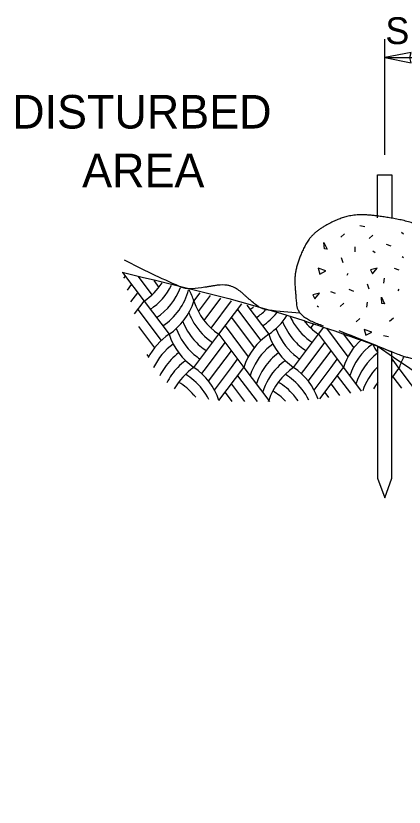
# Model space of a CAD drawing. Extents: x 99862 to 103680, y 99470 to 102076.
# Drawn here: x 101486.6 to 101717.9, y 100885.4 to 101357.1 of the extents above; entities that cross this region are included whole.
import ezdxf

# ---------------------------------------------------------------- set-up
doc = ezdxf.new("R2010")
doc.units = 0
for name, color, linetype in [('Level 1', 7, 'Continuous'), ('Level 15', 7, 'Continuous'), ('Level 2', 7, 'Continuous'), ('Level 20', 7, 'Continuous'), ('Level 5', 7, 'Continuous'), ('Level 8', 7, 'Continuous')]:
    doc.layers.add(name, color=color, linetype=linetype)

msp = doc.modelspace()

# ---------------------------------------------------------------- linework, layer by layer
at = {"layer": 'Level 1'}
msp.add_line((101701.88, 101160.32), (101681.85, 101168.11), dxfattribs=at)
msp.add_open_spline([(101679, 101169.6), (101713.94, 101155.29), (101722.33, 101152.8), (101733.67, 101150.75), (101742.6, 101156.76), (101752.6, 101167.59), (101757.92, 101185.54), (101757.37, 101195.19), (101755.63, 101199.86), (101754.11, 101209.17), (101741.6, 101223.5), (101725.73, 101233.48), (101704.82, 101237.69), (101688.7, 101238.98), (101676.01, 101235.17), (101662.34, 101226.63), (101656.02, 101214.64), (101652.47, 101202.67), (101653.18, 101191.71), (101654.52, 101177.27), (101669.65, 101172.39)], degree=2, dxfattribs=at)
at = {"layer": 'Level 15'}
for p, q in [((101706.31, 101274.26), (101706.31, 101343.26)), ((101706.31, 101332.26), (101960.08, 101332.26))]:
    msp.add_line(p, q, dxfattribs=at)
msp.add_lwpolyline([(101706.31, 101332.26), (101722.04, 101329.18), (101721.31, 101332.26), (101722.04, 101335.35)], close=True, dxfattribs=at)
at = {"layer": 'Level 2'}
for p, q in [((101691.48, 101232.14), (101694.43, 101231.6)), ((101680.12, 101225.26), (101682.39, 101227.21)), ((101716.35, 101228.18), (101717.6, 101227.24)), ((101697, 101224.35), (101699.28, 101226.31)), ((101688.6, 101219.45), (101688.6, 101216.45)), ((101707.16, 101221.04), (101709.95, 101219.92)), ((101681.66, 101209.93), (101680.65, 101212.76)), ((101699.32, 101216.92), (101700.57, 101215.98)), ((101716.67, 101213.64), (101717.45, 101213.01)), ((101684.39, 101203.47), (101683.77, 101202.37)), ((101711.99, 101206.71), (101714.77, 101205.59)), ((101705.95, 101200.65), (101705.65, 101197.67)), ((101684.89, 101194.07), (101687.72, 101193.06)), ((101697.09, 101194.23), (101696.08, 101197.06)), ((101714.79, 101194.24), (101714.16, 101193.14)), ((101674, 101192.83), (101676.78, 101191.71)), ((101679.69, 101183.86), (101681.89, 101185.9)), ((101695.84, 101186.32), (101695.55, 101183.34)), ((101666.18, 101184.23), (101666.96, 101183.6)), ((101689.31, 101174.72), (101691.59, 101176.67)), ((101709.21, 101175.02), (101711.49, 101176.98)), ((101705.65, 101166.51), (101708.61, 101165.98)), ((101702.13, 101160.21), (101702.13, 101081.58)), ((101710.49, 101156.68), (101702.13, 101160.21)), ((101710.49, 101081.58), (101710.49, 101156.68)), ((101702.13, 101081.58), (101706.31, 101069.69)), ((101706.31, 101069.69), (101710.49, 101081.58))]:
    msp.add_line(p, q, dxfattribs=at)
msp.add_lwpolyline([(101702.13, 101236.77), (101702.13, 101262.26), (101710.49, 101262.26), (101710.49, 101236.54)], dxfattribs=at)
for points in [[(101670.09, 101221.93), (101671.96, 101218.02), (101670.4, 101218.17)], [(101666.65, 101206.6), (101667.74, 101203.16), (101671.34, 101205.03)], [(101697.91, 101205.71), (101699, 101203.37), (101701.82, 101206.65)], [(101663.52, 101190.79), (101664.62, 101188.45), (101667.43, 101191.73)], [(101704.34, 101189.31), (101706.22, 101185.4), (101704.65, 101185.55)], [(101694, 101170.15), (101695.1, 101166.71), (101698.69, 101168.58)]]:
    msp.add_lwpolyline(points, close=True, dxfattribs=at)
at = {"layer": 'Level 5'}
for p, q in [((101550.2, 101204.14), (101562.99, 101187.09)), ((101550.9, 101200.67), (101551.85, 101201.94)), ((101559.45, 101201.71), (101567.64, 101190.79)), ((101568.69, 101199.29), (101571.72, 101195.25)), ((101553.02, 101193.61), (101555.56, 101196.99)), ((101555.15, 101186.55), (101559.28, 101192.04)), ((101592.69, 101187.09), (101596.38, 101192.02)), ((101595.36, 101180.76), (101602.58, 101190.39)), ((101557.28, 101179.48), (101562.99, 101187.09)), ((101562.99, 101187.09), (101577.84, 101167.29)), ((101598.8, 101175.45), (101608.78, 101188.76)), ((101602.88, 101170.99), (101614.99, 101187.13)), ((101607.54, 101167.29), (101621.19, 101185.5)), ((101624.16, 101184.72), (101637.23, 101167.29)), ((101559.28, 101182.14), (101573.18, 101163.6)), ((101618.67, 101182.14), (101632.58, 101163.6)), ((101614.96, 101177.19), (101628.5, 101159.14)), ((101559.58, 101171.83), (101569.11, 101159.14)), ((101611.25, 101172.24), (101625.06, 101153.83)), ((101662.28, 101170.99), (101664.16, 101173.49)), ((101666.93, 101167.29), (101670.08, 101171.49)), ((101671.6, 101170.97), (101684.45, 101153.83)), ((101592.69, 101147.5), (101607.54, 101167.29)), ((101607.54, 101167.29), (101622.38, 101147.5)), ((101652.08, 101147.5), (101666.93, 101167.29)), ((101666.93, 101167.29), (101681.78, 101147.5)), ((101681.67, 101167.44), (101687.9, 101159.14)), ((101600.11, 101147.5), (101611.25, 101162.34)), ((101659.51, 101147.5), (101670.64, 101162.34)), ((101691.37, 101164.4), (101691.98, 101163.6)), ((101607.54, 101147.5), (101614.96, 101157.4)), ((101666.93, 101147.5), (101674.36, 101157.4)), ((101564.57, 101155.29), (101565.66, 101153.83)), ((101614.96, 101147.5), (101618.67, 101152.45)), ((101674.36, 101147.5), (101678.07, 101152.45)), ((101710.49, 101152.62), (101714.79, 101146.88)), ((101710.49, 101151.04), (101711.08, 101151.83)), ((101717.16, 101153.63), (101717.47, 101153.22)), ((101597.34, 101143.8), (101600.11, 101147.5)), ((101601.42, 101139.34), (101607.54, 101147.5)), ((101604.86, 101134.03), (101614.96, 101147.5)), ((101607.56, 101127.73), (101622.38, 101147.5)), ((101622.38, 101147.5), (101637.23, 101127.7)), ((101656.74, 101143.8), (101659.51, 101147.5)), ((101660.81, 101139.34), (101666.93, 101147.5)), ((101664.26, 101134.03), (101674.36, 101147.5)), ((101667.72, 101128.75), (101681.78, 101147.5)), ((101681.78, 101147.5), (101692.37, 101133.37)), ((101710.49, 101141.14), (101714.79, 101146.88)), ((101714.79, 101146.88), (101728.85, 101128.13)), ((101618.67, 101142.55), (101630.25, 101127.11)), ((101678.07, 101142.55), (101685.92, 101132.08)), ((101614.96, 101137.6), (101622.83, 101127.1)), ((101674.36, 101137.6), (101679.44, 101130.82)), ((101711.08, 101141.93), (101716.24, 101135.05)), ((101611.25, 101132.65), (101615.28, 101127.26)), ((101670.64, 101132.65), (101672.91, 101129.62))]:
    msp.add_line(p, q, dxfattribs=at)
for centre, start, end in [((101542.03, 101218.28), 303.9036, 327.3046), ((101545.74, 101213.33), 303.9036, 333.3749), ((101549.45, 101208.38), 303.9036, 339.3118), ((101553.16, 101203.43), 303.9036, 345.1848), ((101556.88, 101175.7), 17.6434, 28.6671), ((101556.88, 101198.48), 303.9036, 342.3566), ((101628.5, 101198.48), 197.6435, 236.0964), ((101624.78, 101193.53), 200.8778, 211.332), ((101605.14, 101213.33), 303.9036, 307.854), ((101608.85, 101208.38), 303.9036, 314.9212), ((101612.56, 101203.43), 303.9036, 321.5084), ((101616.27, 101198.48), 303.9036, 327.776), ((101684.18, 101193.53), 204.5186, 211.332), ((101687.89, 101198.48), 217.8205, 236.0964), ((101617.36, 101183.63), 200.2432, 228.9599), ((101621.07, 101188.58), 201.4344, 220.9416), ((101624.78, 101193.53), 211.3319, 236.0964), ((101676.76, 101183.63), 200.2432, 228.9599), ((101680.47, 101188.58), 201.4344, 220.9416), ((101684.18, 101193.53), 211.3319, 236.0964), ((101598.8, 101136.11), 123.9036, 153.0009), ((101613.65, 101178.68), 197.6434, 236.0964), ((101658.19, 101136.11), 123.9036, 162.3566), ((101673.04, 101178.68), 197.6434, 236.0964), ((101602.51, 101131.16), 126.3063, 154.2238), ((101621.07, 101188.58), 220.9415, 236.0964), ((101661.91, 101131.16), 126.3063, 154.2266), ((101680.47, 101188.58), 220.9415, 236.0964), ((101717.59, 101136.11), 132.0728, 162.3566), ((101721.3, 101131.16), 126.3439, 162.3566), ((101732.44, 101178.68), 207.366, 216.2473), ((101606.22, 101126.21), 127.1006, 145.4911), ((101665.62, 101126.21), 127.1006, 145.4911), ((101609.94, 101121.26), 126.331, 135.7128), ((101617.36, 101183.63), 228.9599, 236.0964), ((101669.33, 101121.26), 126.331, 135.7128), ((101676.75, 101183.63), 228.9599, 236.0964), ((101725.01, 101126.21), 127.5094, 162.3566), ((101750.6, 101135.49), 151.4846, 162.3566), ((101602.51, 101131.16), 154.2238, 154.2266), ((101606.22, 101126.21), 145.491, 154.2219), ((101609.94, 101121.26), 135.7127, 153.066), ((101613.65, 101116.31), 123.9036, 150.7661), ((101571.73, 101116.31), 17.6985, 56.0963), ((101661.91, 101131.16), 154.2265, 162.3566), ((101665.62, 101126.21), 145.491, 162.3566), ((101669.33, 101121.26), 135.7127, 162.3566), ((101673.04, 101116.31), 123.9036, 162.3566), ((101631.12, 101116.31), 19.1062, 56.0963), ((101721.3, 101131.16), 152.6361, 154.2266), ((101728.73, 101121.26), 135.7127, 160.9102), ((101728.73, 101121.26), 135.0466, 135.7128), ((101568.01, 101111.36), 48.9597, 58.5465), ((101627.41, 101111.36), 48.9597, 58.5465), ((101564.3, 101106.41), 40.9413, 59.3021), ((101568.01, 101111.36), 26.9212, 48.9597), ((101623.7, 101106.41), 40.9413, 59.3021), ((101627.41, 101111.36), 26.4059, 48.9597), ((101732.44, 101116.31), 143.7527, 150.5433), ((101619.99, 101101.46), 43.6268, 58.4874), ((101564.3, 101106.41), 38.3324, 40.9414), ((101623.7, 101106.41), 34.469, 40.9414), ((101601.42, 101139.09), 341.5174, 342.3566), ((101616.27, 101096.51), 54.7248, 56.0964)]:
    msp.add_arc(centre, 37.58, start, end, dxfattribs=at)
for points in [[(101549.82, 101204.24), (101651.18, 101177.63), (101701.91, 101160.36)], [(101701.91, 101160.36), (102021.08, 100961.71), (102190.93, 100885.35)]]:
    msp.add_spline(points, degree=3, dxfattribs=at)
at = {"layer": 'Level 8'}
msp.add_spline([(101655.66, 101179.9), (101636.95, 101181.67), (101635.32, 101181.94), (101633.77, 101182.43), (101630.84, 101183.94), (101625.46, 101188.3), (101624.13, 101189.46), (101622.82, 101190.63), (101621.51, 101191.8), (101620.17, 101192.94), (101617.36, 101194.81), (101614.35, 101196.06), (101613.46, 101196.28), (101612.55, 101196.45), (101606.92, 101196.52), (101604.97, 101196.24), (101603.02, 101195.92), (101601.07, 101195.59), (101599.12, 101195.28), (101591.38, 101194.36), (101587.68, 101194.64), (101585.89, 101195.08), (101584.16, 101195.76), (101551.28, 101211.4)], degree=3, dxfattribs=at)

# ---------------------------------------------------------------- texts
at = {"layer": 'Level 20'}
for s, height, p in [('SPACING VARIES (TYP.)', 16, (101706.71, 101340.26)), ('DISTURBED', 20, (101484.37, 101289.93)), ('AREA', 20, (101526.06, 101254.93))]:
    msp.add_text(s, height=height, dxfattribs=at).set_placement(p)

doc.saveas('drawing.dxf')
